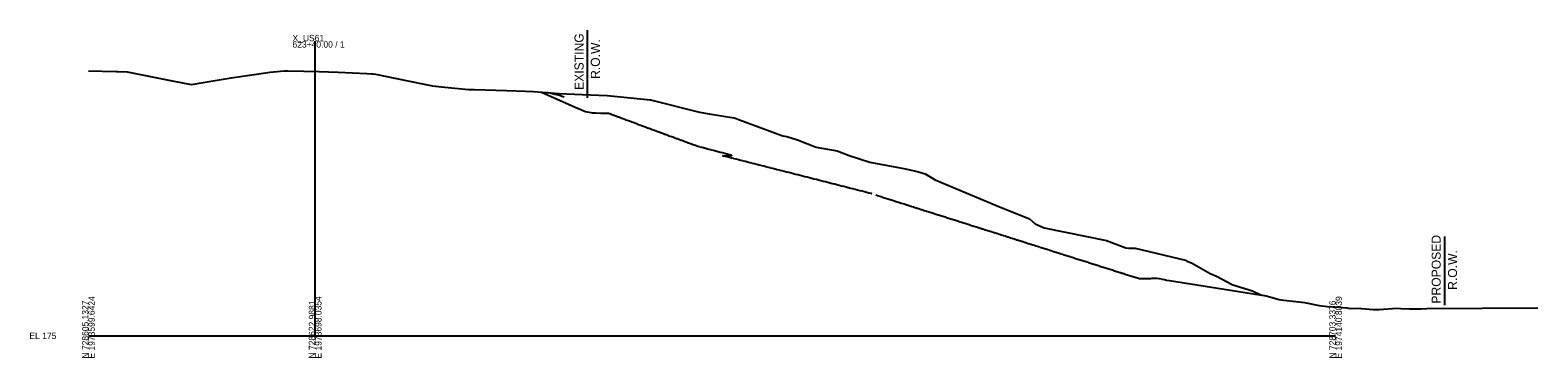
# Model space of a CAD drawing. Extents: x -26 to 1629, y -25 to 9635.
# Drawn here: x -26 to 639, y 8490 to 8635 of the extents above; entities that cross this region are included whole.
import ezdxf

# ---------------------------------------------------------------- set-up
doc = ezdxf.new("R2010")
doc.units = 0
for name, color, linetype in [('Draft_XS_Grid', 7, 'Continuous'), ('DTM_X_GROUND', 7, 'Continuous'), ('XS_CELL', 7, 'Continuous'), ('XS_P_GROUND', 7, 'Continuous'), ('XS_P_ROW', 7, 'Continuous'), ('XS_X_ROW', 7, 'Continuous')]:
    doc.layers.add(name, color=color, linetype=linetype)

msp = doc.modelspace()

# ---------------------------------------------------------------- linework, layer by layer
at = {"layer": 'DTM_X_GROUND'}
msp.add_lwpolyline([(0, 8616.96), (12.26, 8616.68), (13.09, 8616.67), (13.18, 8616.66), (17.16, 8616.43), (36.26, 8612.67), (45.28, 8610.89), (47.92, 8611.33), (62.96, 8613.84), (80.12, 8616.3), (84.65, 8616.85), (86.31, 8616.93), (87.82, 8617.01), (95.06, 8616.85), (101.61, 8616.69), (110.1, 8616.3), (122.78, 8615.72), (124.85, 8615.61), (125.59, 8615.57), (126.6, 8615.41), (140.06, 8612.66), (150.21, 8610.63), (151.76, 8610.29), (155.72, 8609.94), (167.67, 8608.74), (167.97, 8608.76), (170.31, 8608.69), (184.39, 8608.31), (192.81, 8607.97), (196.29, 8607.79), (207.63, 8606.97), (217.8, 8606.45), (228.83, 8606.09), (246.48, 8604.36), (247.63, 8604.19), (247.82, 8604.15), (248.08, 8604.09), (248.48, 8604.01), (269.43, 8598.77), (273.79, 8597.95), (284.65, 8596.27), (284.9, 8596.22), (287.11, 8595.39), (300.67, 8590.28), (305.4, 8588.54), (306.18, 8588.26), (307.96, 8587.97), (312.7, 8586.43), (320.96, 8583.2), (330.13, 8581.66), (335.5, 8579.6), (344.63, 8576.6), (360.37, 8573.71), (366.09, 8572.42), (368.96, 8571.54), (373.48, 8568.87), (400.72, 8557.43), (415, 8551.69), (417.51, 8549.37), (421.56, 8547.72), (448.92, 8542.14), (457.53, 8538.82), (458.76, 8538.71), (461.57, 8538.7), (483.84, 8533.35), (484.45, 8533.03), (486.45, 8532.3), (494.63, 8527.49), (497.43, 8526.4), (504.46, 8522.63), (506.17, 8522.05), (513.41, 8519.81), (517.01, 8518.14), (519.46, 8517.7), (525.15, 8516.09), (525.84, 8515.97), (535.09, 8514.87), (536.36, 8514.72), (542.72, 8513.48), (546.44, 8513.03), (549.7, 8512.79), (554.97, 8512.32), (555.69, 8512.19), (557.94, 8512.14), (559.73, 8512.21), (566.65, 8511.67), (568.25, 8511.58), (569.21, 8511.62), (577.03, 8512.27), (578.71, 8512.11), (582.6, 8511.92), (586.67, 8511.94), (587.65, 8511.98), (590.26, 8512.03), (639.2, 8512.32)], dxfattribs=at)
at = {"layer": 'XS_CELL'}
for p, q in [((100, 8500), (100, 8630)), ((0, 8500), (100, 8500)), ((100, 8500), (550, 8500))]:
    msp.add_line(p, q, dxfattribs=at)
at = {"layer": 'XS_P_GROUND'}
for points in [[(345.53, 8562.7), (345.52, 8562.7), (345.26, 8562.77), (345.22, 8562.78), (344.25, 8563.02), (344.21, 8563.03), (343.24, 8563.28), (343.2, 8563.29), (342.23, 8563.54), (342.19, 8563.55), (341.22, 8563.79), (341.18, 8563.8), (340.21, 8564.05), (340.17, 8564.06), (339.2, 8564.31), (339.16, 8564.32), (338.19, 8564.56), (338.15, 8564.58), (337.18, 8564.82), (337.13, 8564.83), (336.17, 8565.08), (336.12, 8565.09), (335.16, 8565.34), (335.11, 8565.35), (334.15, 8565.59), (334.1, 8565.6), (333.14, 8565.85), (333.09, 8565.86), (332.13, 8566.11), (332.08, 8566.12), (331.12, 8566.36), (331.07, 8566.38), (330.11, 8566.62), (330.06, 8566.63), (329.1, 8566.88), (329.05, 8566.89), (328.09, 8567.13), (328.04, 8567.15), (327.08, 8567.39), (327.03, 8567.4), (326.07, 8567.65), (326.02, 8567.66), (325.06, 8567.9), (325.01, 8567.92), (324.05, 8568.16), (324, 8568.17), (323.04, 8568.42), (322.99, 8568.43), (322.03, 8568.68), (321.98, 8568.69), (321.02, 8568.93), (320.97, 8568.95), (320.01, 8569.19), (319.96, 8569.2), (319, 8569.45), (318.95, 8569.46), (317.99, 8569.7), (317.94, 8569.72), (316.98, 8569.96), (316.93, 8569.97), (315.97, 8570.22), (315.92, 8570.23), (314.96, 8570.47), (314.91, 8570.49), (313.95, 8570.73), (313.9, 8570.75), (312.94, 8570.99), (312.89, 8571), (311.93, 8571.25), (311.88, 8571.26), (310.92, 8571.5), (310.87, 8571.52), (309.91, 8571.76), (309.86, 8571.77), (308.9, 8572.02), (308.84, 8572.03), (307.89, 8572.27), (307.83, 8572.29), (306.88, 8572.53), (306.82, 8572.54), (305.87, 8572.79), (305.81, 8572.8), (304.86, 8573.04), (304.8, 8573.06), (303.85, 8573.3), (303.79, 8573.32), (302.84, 8573.56), (302.78, 8573.57), (301.83, 8573.82), (301.77, 8573.83), (300.82, 8574.07), (300.76, 8574.09), (299.81, 8574.33), (299.75, 8574.34), (298.8, 8574.59), (298.74, 8574.6), (297.79, 8574.84), (297.73, 8574.86), (296.78, 8575.1), (296.72, 8575.11), (295.77, 8575.36), (295.71, 8575.37), (294.76, 8575.61), (294.7, 8575.63), (293.75, 8575.87), (293.69, 8575.89), (292.74, 8576.13), (292.68, 8576.14), (291.73, 8576.39), (291.67, 8576.4), (290.72, 8576.64), (290.66, 8576.66), (289.71, 8576.9), (289.65, 8576.91), (288.7, 8577.16), (288.64, 8577.17), (287.69, 8577.41), (287.63, 8577.43), (286.68, 8577.67), (286.62, 8577.69), (285.67, 8577.93), (285.61, 8577.94), (284.66, 8578.18), (284.6, 8578.2), (283.65, 8578.44), (283.59, 8578.46), (282.64, 8578.7), (282.58, 8578.71), (281.63, 8578.95), (281.57, 8578.97), (280.62, 8579.21), (280.57, 8579.22), (279.78, 8579.42), (279.71, 8579.44), (282.74, 8579.4), (283.68, 8579.64), (283.67, 8579.66), (283.61, 8579.68), (282.67, 8579.92), (282.61, 8579.94), (281.67, 8580.19), (281.61, 8580.2), (280.67, 8580.45), (280.61, 8580.46), (279.67, 8580.71), (279.61, 8580.72), (278.67, 8580.97), (278.61, 8580.98), (277.67, 8581.23), (277.61, 8581.25), (276.67, 8581.49), (276.61, 8581.51), (275.67, 8581.75), (275.6, 8581.77), (274.67, 8582.01), (274.6, 8582.03), (273.67, 8582.27), (273.6, 8582.29), (272.67, 8582.53), (272.59, 8582.55), (271.67, 8582.79), (271.59, 8582.82), (270.67, 8583.06), (270.58, 8583.08), (269.67, 8583.32), (269.57, 8583.34), (268.67, 8583.58), (268.57, 8583.61), (267.67, 8583.95), (267.56, 8583.98), (266.67, 8584.31), (266.55, 8584.35), (265.67, 8584.68), (265.54, 8584.72), (264.67, 8585.05), (264.53, 8585.1), (263.67, 8585.42), (263.51, 8585.47), (262.67, 8585.79), (262.49, 8585.85), (261.67, 8586.16), (261.47, 8586.22), (260.67, 8586.53), (260.44, 8586.6), (259.67, 8586.9), (259.4, 8586.99), (258.67, 8587.27), (258.35, 8587.38), (257.67, 8587.64), (257.27, 8587.78), (256.67, 8588), (256.14, 8588.19), (255.67, 8588.37), (254.89, 8588.66), (254.67, 8588.74), (254.21, 8588.91), (253.67, 8589.11), (253.64, 8589.12), (252.67, 8589.48), (252.61, 8589.5), (251.66, 8589.85), (251.61, 8589.87), (250.66, 8590.22), (250.61, 8590.24), (249.66, 8590.59), (249.62, 8590.61), (248.66, 8590.96), (248.62, 8590.97), (247.66, 8591.33), (247.62, 8591.34), (246.66, 8591.7), (246.63, 8591.71), (245.66, 8592.07), (245.63, 8592.08), (244.66, 8592.45), (244.64, 8592.45), (243.66, 8592.82), (243.64, 8592.82), (242.66, 8593.19), (242.64, 8593.19), (241.66, 8593.56), (241.65, 8593.56), (240.66, 8593.93), (240.65, 8593.93), (239.66, 8594.3), (239.65, 8594.3), (238.66, 8594.67), (238.66, 8594.67), (237.66, 8595.04), (237.66, 8595.04), (237.09, 8595.25), (236.68, 8595.41), (236.66, 8595.41), (235.72, 8595.76), (235.66, 8595.78), (234.76, 8596.12), (234.66, 8596.16), (233.79, 8596.48), (233.66, 8596.53), (232.82, 8596.84), (232.66, 8596.9), (231.85, 8597.2), (231.66, 8597.27), (230.88, 8597.56), (230.66, 8597.64), (229.9, 8597.92), (229.66, 8598.01), (229.5, 8598.07), (229.45, 8598.09), (228.76, 8598.11), (226.23, 8598.15), (225.94, 8598.15), (223.82, 8598.25), (222.36, 8598.31), (221.78, 8598.4), (220.05, 8598.68), (219.16, 8598.82), (218.72, 8599), (218.13, 8599.27), (217.78, 8599.42), (217.1, 8599.72), (216.85, 8599.82), (216.06, 8600.17), (215.95, 8600.22), (199.74, 8607.38)], [(209.88, 8605.31), (208.93, 8605.64), (208.85, 8605.67), (207.88, 8606), (207.82, 8606.03), (207.25, 8606.22), (207.22, 8606.24), (206.81, 8606.33), (206.79, 8606.33), (205.79, 8606.56), (205.76, 8606.57), (204.75, 8606.79), (204.73, 8606.8), (203.71, 8607.02), (203.7, 8607.03), (202.67, 8607.25), (202.66, 8607.25), (202.09, 8607.37)], [(347.22, 8562.17), (348, 8561.93), (348.04, 8561.91), (349.01, 8561.6), (349.05, 8561.59), (350.02, 8561.28), (350.06, 8561.27), (351.03, 8560.96), (351.07, 8560.95), (352.04, 8560.64), (352.08, 8560.63), (353.05, 8560.32), (353.09, 8560.31), (354.06, 8560), (354.1, 8559.99), (355.07, 8559.68), (355.11, 8559.67), (355.46, 8559.56), (355.5, 8559.55), (356.12, 8559.35), (356.19, 8559.33), (356.58, 8559.2), (357.13, 8559.03), (357.23, 8559), (357.67, 8558.86), (358.14, 8558.71), (358.49, 8558.6), (359.15, 8558.39), (359.71, 8558.21), (360.16, 8558.07), (360.8, 8557.87), (361.17, 8557.75), (361.84, 8557.53), (362.18, 8557.42), (362.87, 8557.21), (363.19, 8557.1), (363.9, 8556.88), (364.2, 8556.78), (364.92, 8556.56), (365.21, 8556.46), (365.49, 8556.38), (366.22, 8556.14), (366.52, 8556.05), (367.23, 8555.82), (367.55, 8555.72), (368.24, 8555.5), (368.58, 8555.39), (369.25, 8555.18), (369.61, 8555.07), (370.26, 8554.86), (370.64, 8554.74), (371.27, 8554.54), (371.67, 8554.41), (372.28, 8554.22), (372.7, 8554.09), (373.29, 8553.9), (373.72, 8553.76), (374.3, 8553.58), (374.75, 8553.44), (375.31, 8553.26), (375.78, 8553.11), (376.32, 8552.94), (376.8, 8552.79), (377.33, 8552.62), (377.83, 8552.46), (378.34, 8552.3), (378.85, 8552.14), (379.35, 8551.98), (379.87, 8551.81), (380.37, 8551.66), (380.9, 8551.49), (381.38, 8551.34), (381.92, 8551.16), (382.39, 8551.01), (382.94, 8550.84), (383.4, 8550.69), (383.96, 8550.51), (384.41, 8550.37), (384.98, 8550.19), (385.42, 8550.05), (386, 8549.87), (386.43, 8549.73), (387.02, 8549.54), (387.44, 8549.41), (388.04, 8549.22), (388.45, 8549.09), (389.06, 8548.9), (389.46, 8548.77), (390.08, 8548.57), (390.47, 8548.45), (391.1, 8548.25), (391.48, 8548.13), (392.12, 8547.93), (392.49, 8547.81), (393.14, 8547.6), (393.5, 8547.49), (394.16, 8547.28), (394.51, 8547.17), (395.18, 8546.96), (395.52, 8546.85), (396.19, 8546.63), (396.53, 8546.53), (397.21, 8546.31), (397.54, 8546.21), (398.23, 8545.99), (398.55, 8545.89), (399.25, 8545.66), (399.56, 8545.57), (400.26, 8545.34), (400.57, 8545.25), (401.28, 8545.02), (401.58, 8544.93), (402.21, 8544.72), (402.46, 8544.64), (402.55, 8544.62), (402.59, 8544.6), (403.31, 8544.37), (403.6, 8544.28), (404.26, 8544.08), (404.5, 8544), (404.58, 8543.97), (404.61, 8543.96), (405.35, 8543.73), (405.62, 8543.64), (406.36, 8543.41), (406.63, 8543.32), (407.38, 8543.08), (407.64, 8543), (408.4, 8542.76), (408.65, 8542.68), (409.41, 8542.44), (409.66, 8542.36), (410.43, 8542.12), (410.67, 8542.04), (411.44, 8541.8), (411.68, 8541.72), (412.46, 8541.47), (412.69, 8541.4), (413.47, 8541.15), (413.7, 8541.08), (414.49, 8540.83), (414.71, 8540.76), (415.5, 8540.51), (415.72, 8540.44), (416.52, 8540.18), (416.73, 8540.12), (417.53, 8539.86), (417.74, 8539.8), (418.55, 8539.54), (418.75, 8539.48), (419.56, 8539.22), (419.76, 8539.16), (420.58, 8538.9), (420.77, 8538.84), (421.59, 8538.58), (421.78, 8538.52), (422.6, 8538.25), (422.79, 8538.2), (423.62, 8537.93), (423.8, 8537.87), (424.63, 8537.61), (424.81, 8537.55), (425.65, 8537.29), (425.82, 8537.23), (426.66, 8536.97), (426.83, 8536.91), (427.67, 8536.64), (427.84, 8536.59), (428.58, 8536.36), (428.72, 8536.31), (428.83, 8536.28), (428.85, 8536.27), (429.7, 8536), (429.86, 8535.95), (430.72, 8535.68), (430.87, 8535.63), (431.73, 8535.36), (431.88, 8535.31), (432.74, 8535.04), (432.89, 8534.99), (433.76, 8534.71), (433.9, 8534.67), (434.77, 8534.39), (434.91, 8534.35), (435.78, 8534.07), (435.92, 8534.03), (436.8, 8533.75), (436.93, 8533.71), (437.81, 8533.43), (437.94, 8533.39), (438.82, 8533.11), (438.95, 8533.07), (439.84, 8532.79), (439.96, 8532.75), (440.85, 8532.46), (440.97, 8532.43), (441.86, 8532.14), (441.98, 8532.11), (442.87, 8531.82), (442.99, 8531.79), (443.89, 8531.5), (444, 8531.46), (444.9, 8531.18), (445.01, 8531.14), (445.91, 8530.86), (446.02, 8530.82), (446.93, 8530.54), (447.03, 8530.5), (447.94, 8530.21), (448.04, 8530.18), (448.95, 8529.89), (449.05, 8529.86), (449.96, 8529.57), (450.06, 8529.54), (450.98, 8529.25), (451.07, 8529.22), (451.99, 8528.93), (452.08, 8528.9), (453, 8528.61), (453.09, 8528.58), (454.01, 8528.29), (454.1, 8528.26), (454.9, 8528.01), (454.98, 8527.98), (455.1, 8527.94), (455.11, 8527.94), (455.81, 8527.72), (455.87, 8527.7), (456.1, 8527.63), (456.12, 8527.62), (457.05, 8527.32), (457.13, 8527.3), (458.06, 8527), (458.14, 8526.98), (459.08, 8526.68), (459.15, 8526.66), (460.09, 8526.36), (460.16, 8526.34), (461.1, 8526.04), (461.17, 8526.02), (462.11, 8525.72), (462.18, 8525.7), (463.12, 8525.4), (463.19, 8525.38), (463.51, 8525.34), (463.7, 8525.33), (464.35, 8525.33), (464.9, 8525.32), (465.56, 8525.32), (466.1, 8525.32), (466.76, 8525.34), (467.31, 8525.35), (467.89, 8525.36), (468.56, 8525.39), (469.18, 8525.41), (469.86, 8525.45), (470.55, 8525.49), (471.23, 8525.53), (471.33, 8525.51), (472.21, 8525.33), (472.33, 8525.3), (473.3, 8525.1), (473.43, 8525.08), (474.39, 8524.88), (474.53, 8524.85), (475.49, 8524.65), (475.63, 8524.63), (476.58, 8524.43), (476.7, 8524.41), (519.46, 8517.7)]]:
    msp.add_lwpolyline(points, dxfattribs=at)
at = {"layer": 'XS_P_ROW'}
msp.add_line((598, 8543.86), (598, 8513.54), dxfattribs=at)
at = {"layer": 'XS_X_ROW'}
msp.add_line((220, 8634.9), (220, 8605), dxfattribs=at)

# ---------------------------------------------------------------- texts
at = {"layer": 'Draft_XS_Grid'}
msp.add_text('-', height=0.0001, dxfattribs=at).set_placement((0, 8500))
at = {"layer": 'XS_CELL'}
for s, p in [('X_US61', (90, 8630)), ('623+40.00 / 1', (90, 8627.2)), ('EL 175', (-26, 8498.6))]:
    msp.add_text(s, height=2.8, dxfattribs=at).set_placement(p)
for s, p in [('E 1973599.6424', (2.8, 8490)), ('E 1973698.0354', (102.8, 8490)), ('E 1974140.8039', (552.8, 8490)), ('N 728605.1327', (0, 8490)), ('N 728622.9881', (100, 8490)), ('N 728703.3376', (550, 8490))]:
    msp.add_text(s, height=2.8, rotation=90, dxfattribs=at).set_placement(p)
at = {"layer": 'XS_P_ROW'}
for s, p in [('PROPOSED', (596.37, 8514.24)), ('R.O.W.', (603.57, 8520.32))]:
    msp.add_text(s, height=4, rotation=90, dxfattribs=at).set_placement(p)
at = {"layer": 'XS_X_ROW'}
for s, p in [('EXISTING', (218.37, 8608.54)), ('R.O.W.', (225.57, 8613.38))]:
    msp.add_text(s, height=4, rotation=90, dxfattribs=at).set_placement(p)

doc.saveas('drawing.dxf')
